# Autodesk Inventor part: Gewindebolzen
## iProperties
Company: HERDT-Verlag
Shininess: 64.0
Length Units: 11269
Angle Units: 11279
Time Units: 11290
Mass Units: 11283
Length Display Precision: 3
Angle Display Precision: 2
Compacted: True
Part Number: Gewindebolzen
Document SubType Name: Modeling
Created: 2006-01
Material: 1.7225 42 CrMo 4(Vergüt.st.)
Designer: Eichenseer
Manufacturer: Standard
Standards Organization: Custom
Project: Inventor 11 - Grundkurs
Engineer: Käs
Description: 61059
Checked By: G. Lehmann
Engr Approved By: M. Grouls
Density: 0.0
Volumn: 0.0
Area: 0.0
PropertySet Name: Model Information
Control State: 0
Master: False
Checked Out: False
Author: P. Tropf
Subject: Inventor 10 - Grundkurs
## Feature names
1. Extrusion1
2. Drehung1 [Revolution]
3. Fase1 [Chamfer]
4. Rundung1 [Fillet]
